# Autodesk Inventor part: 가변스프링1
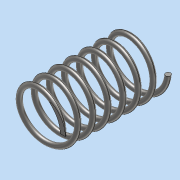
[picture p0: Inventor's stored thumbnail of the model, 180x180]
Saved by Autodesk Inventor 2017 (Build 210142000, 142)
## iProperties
Part Number: 가변스프링1
Material: 스테인레스 스틸
Document SubType Name: Modeling
Designer: MRC
Density: 8 g/cm^3
Appearance: 반연마
Mass: 10.9961 g
Surface Area: 27.6971 cm^2
Volume: 1.37451 cm^3
Author: MRC
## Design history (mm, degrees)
sketch "스케치1"
  geometry: L1 (0, 41.411)-(10, 41.411); L2 (10, 41.411)-(10, 0); L3 (10, 0)-(0, 0); L4 (0, 0)-(0, 41.411); C1 r 1 at (10, 0); 1 further point
  constraints: 8 end point, 2 coincident, 2 parallel, 1 centre point, 1 horizontal, 1 perpendicular
  dimensions: "d0" = 41.4112 distance of L1.end L2.end (derived); "d1" = 20 diameter of L2 L4; "d2" = 2 diameter of C1
feature "코일1" sketch "스케치1" pitch "d3" = 10; turns "d5" = 7; dims "d4" = 41.4112 (= d0), "d6" = 0, angle "d7" = 90 deg, angle "d8" = 90 deg, "d9" = 0, "d10" = 0
sketch "스케치2"
  geometry: L1 (-19.444, 50)-(19.444, 50); L2 (19.444, 50)-(19.444, 0); L3 (19.444, 0)-(-19.444, 0); L4 (-19.444, 0)-(-19.444, 50); 2 further points
  constraints: 8 end point, 2 parallel, 1 coincident, 1 horizontal, 1 midpoint, 1 perpendicular
  dimensions: "d11" = 50 distance of L1.end L2.end; "d12" = 38.88889 distance of L1.start L1.end
extrude "돌출1" sketch "스케치2" stored distance "d13" = 0; taper "d14" = 0 deg
node "솔리드1"
